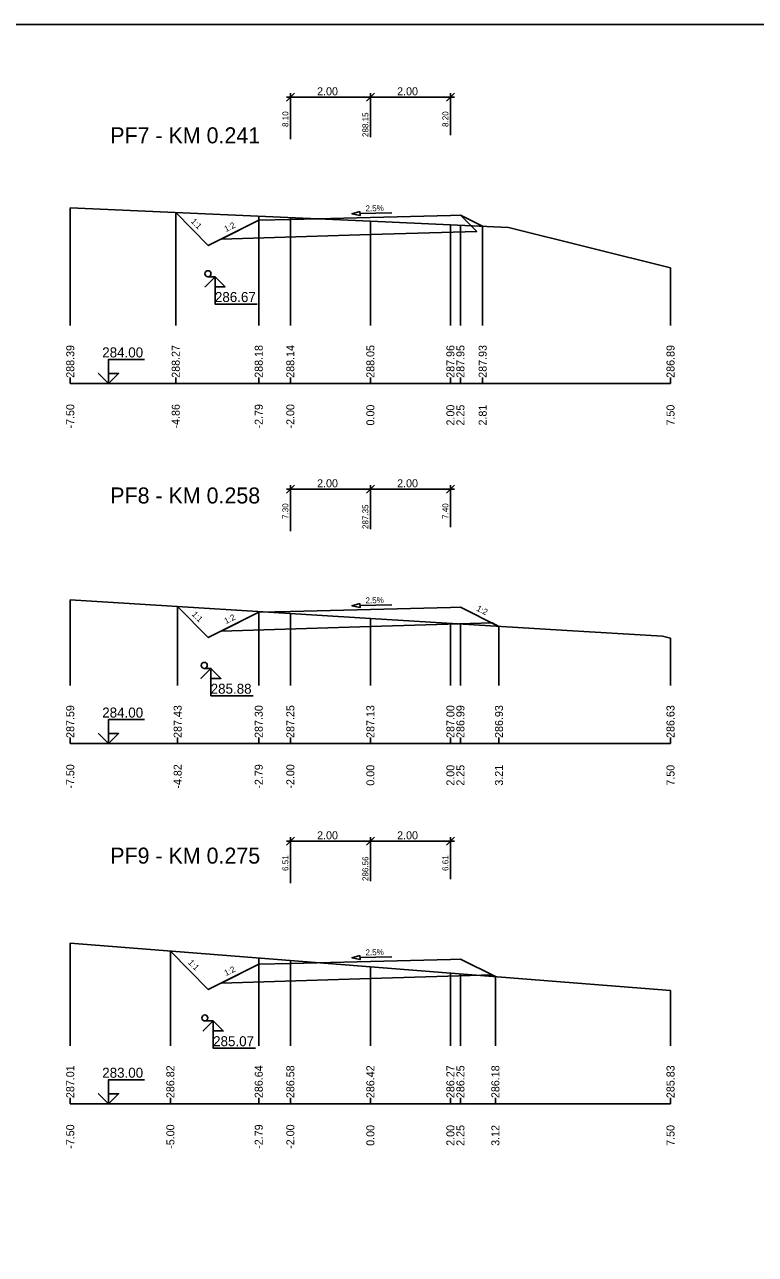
# Model space of a CAD drawing. Extents: x -5 to 1895, y -2 to 602.
# Drawn here: x 438.6 to 621.2, y 289.4 to 596.7 of the extents above; entities that cross this region are included whole.
import ezdxf

# ---------------------------------------------------------------- set-up
doc = ezdxf.new("R2010")
doc.units = 0
for name, color, linetype in [('KOTA', 7, 'Continuous'), ('KOTA_DELKY', 7, 'Continuous'), ('KOTA_DELKY_CONT', 7, 'Continuous'), ('KRIZENI', 7, 'Continuous'), ('NS_TELESO_VOZOVKY', 7, 'Continuous'), ('NS_V_PF', 7, 'Continuous'), ('REZY_PF_PUVODNI', 7, 'Continuous'), ('SESTAVY_REZU_PF', 7, 'Continuous'), ('SKLON', 7, 'Continuous'), ('SVK', 7, 'Continuous')]:
    doc.layers.add(name, color=color, linetype=linetype)

msp = doc.modelspace()

# ---------------------------------------------------------------- linework, layer by layer
msp.add_lwpolyline([(0, 596.67), (1890, 596.67), (1890, 2.67), (0, 2.67)], close=True)
at = {"layer": 'KOTA'}
for points in [[(486.2, 533.66), (483.7, 531.16), (486.2, 533.66), (486.2, 526.84), (496.74, 526.84)], [(484.41, 533.66), (486.2, 533.66)], [(486.2, 533.66), (488.7, 531.16), (486.2, 531.16), (486.2, 533.66)], [(486.2, 533.66), (488.7, 531.16), (486.2, 531.16)], [(459.57, 507), (457.07, 509.5), (459.57, 507), (459.57, 513), (468.57, 513)], [(459.57, 507), (462.07, 509.5), (459.57, 509.5), (459.57, 507)], [(459.57, 507), (462.07, 509.5), (459.57, 509.5)], [(485.14, 435.78), (482.64, 433.28), (485.14, 435.78), (485.14, 428.96), (495.68, 428.96)], [(483.49, 435.78), (485.14, 435.78)], [(485.14, 435.78), (487.64, 433.28), (485.14, 433.28), (485.14, 435.78)], [(485.14, 435.78), (487.64, 433.28), (485.14, 433.28)], [(459.57, 417), (457.07, 419.5), (459.57, 417), (459.57, 423), (468.57, 423)], [(459.57, 417), (462.07, 419.5), (459.57, 419.5), (459.57, 417)], [(459.57, 417), (462.07, 419.5), (459.57, 419.5)], [(485.75, 347.7), (483.25, 345.2), (485.75, 347.7), (485.75, 340.88), (496.29, 340.88)], [(483.63, 347.7), (485.75, 347.7)], [(485.75, 347.7), (488.25, 345.2), (485.75, 345.2), (485.75, 347.7)], [(485.75, 347.7), (488.25, 345.2), (485.75, 345.2)], [(459.57, 327), (457.07, 329.5), (459.57, 327), (459.57, 333), (468.57, 333)], [(459.57, 327), (462.07, 329.5), (459.57, 329.5), (459.57, 327)], [(459.57, 327), (462.07, 329.5), (459.57, 329.5)]]:
    msp.add_lwpolyline(points, dxfattribs=at)
at = {"layer": 'KOTA_DELKY'}
for points in [[(504, 577.5), (506, 579.5)], [(504, 578.5), (526, 578.5)], [(505, 568), (505, 579.5)], [(524, 577.5), (526, 579.5)], [(524, 577.5), (526, 579.5)], [(524, 578.5), (546, 578.5)], [(525, 568.5), (525, 579.5)], [(525, 568.5), (525, 579.5)], [(544, 577.5), (546, 579.5)], [(545, 569), (545, 579.5)], [(504, 479.54), (506, 481.54)], [(504, 480.54), (526, 480.54)], [(505, 470.04), (505, 481.54)], [(524, 479.54), (526, 481.54)], [(524, 479.54), (526, 481.54)], [(524, 480.54), (546, 480.54)], [(525, 470.54), (525, 481.54)], [(525, 470.54), (525, 481.54)], [(544, 479.54), (546, 481.54)], [(545, 471.04), (545, 481.54)], [(504, 391.58), (506, 393.58)], [(505, 382.08), (505, 393.58)], [(524, 391.58), (526, 393.58)], [(524, 391.58), (526, 393.58)], [(525, 382.58), (525, 393.58)], [(525, 382.58), (525, 393.58)], [(544, 391.58), (546, 393.58)], [(545, 383.08), (545, 393.58)], [(504, 392.58), (526, 392.58)], [(524, 392.58), (546, 392.58)]]:
    msp.add_lwpolyline(points, dxfattribs=at)
at = {"layer": 'KRIZENI'}
for centre in [(484.41, 534.41), (483.49, 436.53), (483.63, 348.45)]:
    msp.add_circle(centre, 0.75, dxfattribs=at)
at = {"layer": 'NS_TELESO_VOZOVKY'}
for points in [[(525, 548.5), (545, 549), (547.5, 549.07), (551.57, 545), (525, 544.2), (487.74, 543.09), (497.1, 547.81), (505, 548), (525, 548.5)], [(525, 450.54), (545, 451.04), (547.5, 451.1), (557.14, 446.28), (555.4, 447.15), (525, 446.24), (487.74, 445.12), (497.1, 449.84), (505, 450.04), (525, 450.54)], [(525, 362.58), (545, 363.08), (547.5, 363.14), (556.24, 358.77), (555.4, 359.19), (525, 358.28), (487.74, 357.16), (497.1, 361.88), (505, 362.08), (525, 362.58)]]:
    msp.add_lwpolyline(points, dxfattribs=at)
at = {"layer": 'NS_V_PF'}
for points in [[(476.36, 549.71), (484.47, 541.43), (497.1, 547.81), (505, 548), (525, 548.5), (545, 549), (547.5, 549.07), (553.06, 546.29)], [(476.84, 451.25), (484.47, 443.47), (497.1, 449.84), (505, 450.04), (525, 450.54), (545, 451.04), (547.5, 451.1), (557.14, 446.28)], [(475.02, 365.15), (484.47, 355.51), (497.1, 361.88), (505, 362.08), (525, 362.58), (545, 363.08), (547.5, 363.14), (556.24, 358.77)]]:
    msp.add_lwpolyline(points, dxfattribs=at)
at = {"layer": 'REZY_PF_PUVODNI'}
for points in [[(450, 550.88), (525, 547.54), (559.5, 546), (600, 535.86)], [(450, 452.91), (525, 448.27), (572.73, 445.32), (597.96, 443.85), (600, 443.33)], [(450, 367.12), (525, 361.23), (525, 361.23), (600, 355.34)]]:
    msp.add_lwpolyline(points, dxfattribs=at)
at = {"layer": 'SESTAVY_REZU_PF'}
for points in [[(450, 507), (600, 507)], [(450, 417), (600, 417)], [(450, 327), (600, 327)]]:
    msp.add_lwpolyline(points, dxfattribs=at)
at = {"layer": 'SKLON'}
for points in [[(522.39, 549.94), (520.4, 549.39), (522.41, 548.94)], [(522.39, 451.98), (520.4, 451.43), (522.41, 450.98)], [(522.39, 364.02), (520.4, 363.47), (522.41, 363.02)]]:
    msp.add_lwpolyline(points, close=True, dxfattribs=at)
for points in [[(522.39, 549.94), (520.4, 549.39), (522.41, 548.94), (522.39, 549.94)], [(522.4, 549.44), (530.4, 549.64)], [(522.39, 451.98), (520.4, 451.43), (522.41, 450.98), (522.39, 451.98)], [(522.4, 451.48), (530.4, 451.68)], [(522.39, 364.02), (520.4, 363.47), (522.41, 363.02), (522.39, 364.02)], [(522.4, 363.52), (530.4, 363.72)]]:
    msp.add_lwpolyline(points, dxfattribs=at)
at = {"layer": 'SVK'}
for points in [[(450, 521.5), (450, 550.88)], [(476.36, 521.5), (476.36, 549.71)], [(497.1, 521.5), (497.1, 548.78)], [(505, 521.5), (505, 548.43)], [(525, 521.5), (525, 547.54)], [(545, 521.5), (545, 546.65)], [(547.5, 521.5), (547.5, 546.54)], [(553.06, 521.5), (553.06, 546.29)], [(600, 521.5), (600, 535.86)], [(450, 507), (450, 508.5)], [(476.36, 507), (476.36, 508.5)], [(497.1, 507), (497.1, 508.5)], [(505, 507), (505, 508.5)], [(525, 507), (525, 508.5)], [(545, 507), (545, 508.5)], [(547.5, 507), (547.5, 508.5)], [(553.06, 507), (553.06, 508.5)], [(600, 507), (600, 508.5)], [(450, 431.5), (450, 452.91)], [(476.84, 431.5), (476.84, 451.25)], [(497.1, 431.5), (497.1, 450)], [(505, 431.5), (505, 449.51)], [(525, 431.5), (525, 448.27)], [(545, 431.5), (545, 447.03)], [(547.5, 431.5), (547.5, 446.88)], [(557.14, 431.5), (557.14, 446.28)], [(600, 431.5), (600, 443.33)], [(450, 417), (450, 418.5)], [(476.84, 417), (476.84, 418.5)], [(497.1, 417), (497.1, 418.5)], [(505, 417), (505, 418.5)], [(525, 417), (525, 418.5)], [(545, 417), (545, 418.5)], [(547.5, 417), (547.5, 418.5)], [(557.14, 417), (557.14, 418.5)], [(600, 417), (600, 418.5)], [(450, 341.5), (450, 367.12)], [(475.02, 341.5), (475.02, 365.15)], [(497.1, 341.5), (497.1, 363.42)], [(505, 341.5), (505, 362.8)], [(525, 341.5), (525, 361.23)], [(545, 341.5), (545, 359.66)], [(547.5, 341.5), (547.5, 359.46)], [(556.24, 341.5), (556.24, 358.77)], [(600, 341.5), (600, 355.34)], [(450, 327), (450, 328.5)], [(475.02, 327), (475.02, 328.5)], [(497.1, 327), (497.1, 328.5)], [(505, 327), (505, 328.5)], [(525, 327), (525, 328.5)], [(545, 327), (545, 328.5)], [(547.5, 327), (547.5, 328.5)], [(556.24, 327), (556.24, 328.5)], [(600, 327), (600, 328.5)]]:
    msp.add_lwpolyline(points, dxfattribs=at)

# ---------------------------------------------------------------- texts
at = {"layer": 'KOTA'}
for s, p in [('286.67', (486.15, 527.34)), ('284.00', (457.99, 513.5)), ('285.88', (485.09, 429.46)), ('284.00', (457.99, 423.5)), ('285.07', (485.7, 341.38)), ('283.00', (457.99, 333.5))]:
    msp.add_text(s, height=2.5, dxfattribs=at).set_placement(p)
at = {"layer": 'KOTA_DELKY'}
for p in [(511.69, 579), (531.69, 579), (511.69, 481.04), (531.69, 481.04), (511.69, 393.08), (531.69, 393.08)]:
    msp.add_text('2.00', height=2, dxfattribs=at).set_placement(p)
at = {"layer": 'KOTA_DELKY_CONT'}
for s, p in [('8.10', (504.5, 571.09)), ('8.20', (544.5, 571.09)), ('288.15', (524.5, 568.58)), ('7.30', (504.5, 473.13)), ('287.35', (524.5, 470.62)), ('7.40', (544.5, 473.13)), ('6.51', (504.5, 385.17)), ('286.56', (524.5, 382.66)), ('6.61', (544.5, 385.17))]:
    msp.add_text(s, height=1.5, rotation=90, dxfattribs=at).set_placement(p)
at = {"layer": 'SESTAVY_REZU_PF'}
for s, p in [('PF7 - KM 0.241', (460, 567)), ('PF8 - KM 0.258', (460, 477)), ('PF9 - KM 0.275', (460, 387))]:
    msp.add_text(s, height=4, dxfattribs=at).set_placement(p)
at = {"layer": 'SKLON'}
for s, rotation, p in [('2.5%', 1.4321, (523.8, 549.97)), ('1:1', 314.4213, (480.02, 547.4)), ('1:2', 26.7649, (488.92, 544.8)), ('2.5%', 1.4321, (523.8, 452.01)), ('1:1', 314.4213, (480.26, 449.19)), ('1:2', 26.7649, (488.92, 446.84)), ('1:2', 333.4349, (551.36, 450.29)), ('1:1', 314.4213, (479.35, 362.16)), ('2.5%', 1.4321, (523.8, 364.05)), ('1:2', 26.7649, (488.92, 358.88))]:
    msp.add_text(s, height=1.5, rotation=rotation, dxfattribs=at).set_placement(p)
at = {"layer": 'SVK'}
for s, p in [(' 288.39', (451, 507.67)), (' 288.27', (477.36, 507.67)), (' 288.18', (498.1, 507.67)), (' 288.14', (506, 507.67)), (' 288.05', (526, 507.67)), (' 287.96', (546, 507.67)), (' 287.95', (548.5, 507.67)), (' 287.93', (554.06, 507.67)), (' 286.89', (601, 507.67)), (' -7.50', (451, 495)), (' -4.86', (477.36, 495)), (' -2.79', (498.1, 495)), (' -2.00', (506, 495)), ('  0.00', (526, 495)), ('  2.00', (546, 495)), ('  2.25', (548.5, 495)), ('  2.81', (554.06, 495)), ('  7.50', (601, 495)), (' 287.59', (451, 417.67)), (' 287.43', (477.84, 417.67)), (' 287.30', (498.1, 417.67)), (' 287.25', (506, 417.67)), (' 287.13', (526, 417.67)), (' 287.00', (546, 417.67)), (' 286.99', (548.5, 417.67)), (' 286.93', (558.14, 417.67)), (' 286.63', (601, 417.67)), (' -7.50', (451, 405)), (' -4.82', (477.84, 405)), (' -2.79', (498.1, 405)), (' -2.00', (506, 405)), ('  0.00', (526, 405)), ('  2.00', (546, 405)), ('  2.25', (548.5, 405)), ('  3.21', (558.14, 405)), ('  7.50', (601, 405)), (' 287.01', (451, 327.67)), (' 286.82', (476.02, 327.67)), (' 286.64', (498.1, 327.67)), (' 286.58', (506, 327.67)), (' 286.42', (526, 327.67)), (' 286.27', (546, 327.67)), (' 286.25', (548.5, 327.67)), (' 286.18', (557.24, 327.67)), (' 285.83', (601, 327.67)), (' -7.50', (451, 315)), (' -5.00', (476.02, 315)), (' -2.79', (498.1, 315)), (' -2.00', (506, 315)), ('  0.00', (526, 315)), ('  2.00', (546, 315)), ('  2.25', (548.5, 315)), ('  3.12', (557.24, 315)), ('  7.50', (601, 315))]:
    msp.add_text(s, height=2, rotation=90, dxfattribs=at).set_placement(p)

doc.saveas('drawing.dxf')
